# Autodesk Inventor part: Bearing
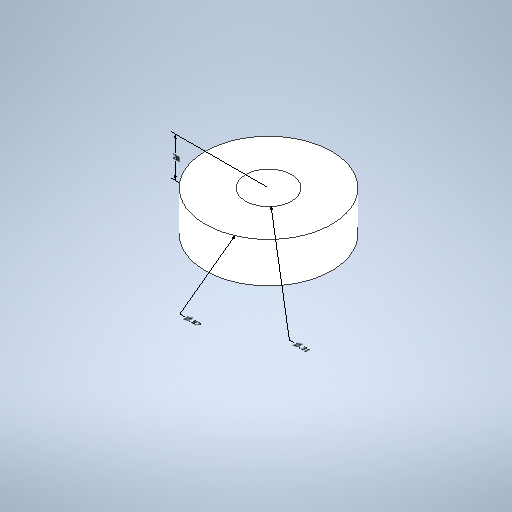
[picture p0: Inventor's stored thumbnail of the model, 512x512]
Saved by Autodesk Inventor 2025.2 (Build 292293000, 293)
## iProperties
Created: 2025-09
Part Number: Bearing
Material: Generic
Document SubType Name: Modeling
Designer: tyler
Density: 1 g/cm^3
Appearance: Default
Author: tyler
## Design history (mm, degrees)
node "Annotations"
  node "Diameter Dimension 1" dims "d5" = 22 (derived)
  node "Diameter Dimension 2" dims "d7" = 8 (derived)
  node "Linear Dimension 1" dims "d8" = 7 (derived)
sketch "Sketch1"
  geometry: C1 r 4 at (0, 0); C2 r 11 at (0, 0); 1 further point
  constraints: 2 centre point, 2 coincident
  dimensions: "d0" = 8 diameter of C1; "d1" = 22 diameter of C2
extrude "Extrusion1" new body sketch "Sketch1" distance "d2" = 7; taper "d3" = 0 deg
body "Solid1"
other parameters: "d4" = 19.70636 (derived), "d6" = 24.35086 (derived)
